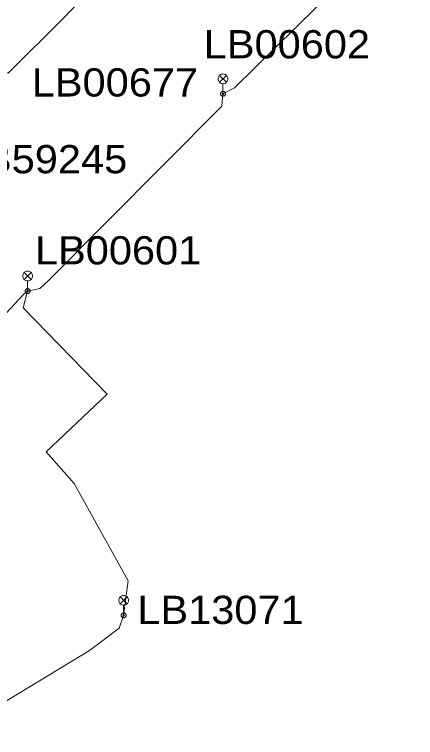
# Model space of a CAD drawing. Extents: x -688049 to -687261, y -973611 to -973038.
# Drawn here: x -687482 to -687451.2, y -973581.7 to -973526.2 of the extents above; entities that cross this region are included whole.
import ezdxf

# ---------------------------------------------------------------- set-up
doc = ezdxf.new("R2010")
doc.units = 0
doc.header["$LTSCALE"] = 0.87
doc.layers.add('1', color=7, linetype='Continuous', lineweight=13)

msp = doc.modelspace()

# ---------------------------------------------------------------- linework, layer by layer
at = {"layer": '1'}
for p, q in [((-687466.235, -973530.865), (-687465.705, -973531.395)), ((-687466.235, -973531.395), (-687465.705, -973530.865)), ((-687465.97, -973532.28), (-687465.97, -973531.505)), ((-687481.225, -973546.005), (-687480.695, -973546.535)), ((-687481.225, -973546.535), (-687480.695, -973546.005)), ((-687480.96, -973547.42), (-687480.96, -973546.645)), ((-687473.855, -973570.905), (-687473.325, -973571.435)), ((-687473.855, -973571.435), (-687473.325, -973570.905)), ((-687473.59, -973572.32), (-687473.59, -973571.545))]:
    msp.add_line(p, q, dxfattribs=at)
for points in [[(-687435.25, -973501.43), (-687435.25, -973502.448), (-687465.092, -973531.834), (-687465.97, -973532.28)], [(-687467.405, -973515.295), (-687467.405, -973515.662), (-687469.111, -973517.285), (-687472.35, -973520.366), (-687478.189, -973526.459), (-687482.459, -973530.691), (-687482.98, -973530.38)], [(-687465.97, -973532.28), (-687466.06, -973533.224), (-687479.338, -973546.595), (-687480.025, -973547.226), (-687480.96, -973547.42)], [(-687480.925, -973547.385), (-687481.31, -973547.725), (-687485.252, -973551.938), (-687492.408, -973546.007), (-687496.766, -973542.227), (-687502.006, -973537.076), (-687502.131, -973537.055)], [(-687473.59, -973572.32), (-687473.238, -973569.66), (-687477.386, -973562.205), (-687479.537, -973559.755), (-687474.856, -973555.338), (-687481.296, -973548.72), (-687480.96, -973547.42)], [(-687488.25, -973581.7), (-687487.316, -973581.393), (-687486.449, -973581.213), (-687476.202, -973575.029), (-687473.932, -973573.292), (-687473.59, -973572.32)]]:
    msp.add_lwpolyline(points, dxfattribs=at)
for points in [[(-687465.595, -973531.13), (-687465.601, -973531.065), (-687465.618, -973531.002), (-687465.645, -973530.942), (-687465.683, -973530.889), (-687465.729, -973530.843), (-687465.782, -973530.805), (-687465.842, -973530.778), (-687465.905, -973530.761), (-687465.97, -973530.755), (-687466.035, -973530.761), (-687466.098, -973530.778), (-687466.158, -973530.805), (-687466.211, -973530.843), (-687466.257, -973530.889), (-687466.295, -973530.942), (-687466.322, -973531.002), (-687466.339, -973531.065), (-687466.345, -973531.13), (-687466.339, -973531.195), (-687466.322, -973531.258), (-687466.295, -973531.318), (-687466.257, -973531.371), (-687466.211, -973531.417), (-687466.158, -973531.455), (-687466.098, -973531.482), (-687466.035, -973531.499), (-687465.97, -973531.505), (-687465.905, -973531.499), (-687465.842, -973531.482), (-687465.782, -973531.455), (-687465.729, -973531.417), (-687465.683, -973531.371), (-687465.645, -973531.318), (-687465.618, -973531.258), (-687465.601, -973531.195)], [(-687465.78, -973532.28), (-687465.783, -973532.247), (-687465.791, -973532.215), (-687465.805, -973532.185), (-687465.824, -973532.158), (-687465.848, -973532.134), (-687465.875, -973532.115), (-687465.905, -973532.101), (-687465.937, -973532.093), (-687465.97, -973532.09), (-687466.003, -973532.093), (-687466.035, -973532.101), (-687466.065, -973532.115), (-687466.092, -973532.134), (-687466.116, -973532.158), (-687466.135, -973532.185), (-687466.149, -973532.215), (-687466.157, -973532.247), (-687466.16, -973532.28), (-687466.157, -973532.313), (-687466.149, -973532.345), (-687466.135, -973532.375), (-687466.116, -973532.402), (-687466.092, -973532.426), (-687466.065, -973532.445), (-687466.035, -973532.459), (-687466.003, -973532.467), (-687465.97, -973532.47), (-687465.937, -973532.467), (-687465.905, -973532.459), (-687465.875, -973532.445), (-687465.848, -973532.426), (-687465.824, -973532.402), (-687465.805, -973532.375), (-687465.791, -973532.345), (-687465.783, -973532.313)], [(-687465.92, -973532.28), (-687465.921, -973532.271), (-687465.923, -973532.263), (-687465.927, -973532.255), (-687465.932, -973532.248), (-687465.938, -973532.242), (-687465.945, -973532.237), (-687465.953, -973532.233), (-687465.961, -973532.231), (-687465.97, -973532.23), (-687465.979, -973532.231), (-687465.987, -973532.233), (-687465.995, -973532.237), (-687466.002, -973532.242), (-687466.008, -973532.248), (-687466.013, -973532.255), (-687466.017, -973532.263), (-687466.019, -973532.271), (-687466.02, -973532.28), (-687466.019, -973532.289), (-687466.017, -973532.297), (-687466.013, -973532.305), (-687466.008, -973532.312), (-687466.002, -973532.318), (-687465.995, -973532.323), (-687465.987, -973532.327), (-687465.979, -973532.329), (-687465.97, -973532.33), (-687465.961, -973532.329), (-687465.953, -973532.327), (-687465.945, -973532.323), (-687465.938, -973532.318), (-687465.932, -973532.312), (-687465.927, -973532.305), (-687465.923, -973532.297), (-687465.921, -973532.289)], [(-687480.585, -973546.27), (-687480.591, -973546.205), (-687480.608, -973546.142), (-687480.635, -973546.082), (-687480.673, -973546.029), (-687480.719, -973545.983), (-687480.772, -973545.945), (-687480.832, -973545.918), (-687480.895, -973545.901), (-687480.96, -973545.895), (-687481.025, -973545.901), (-687481.088, -973545.918), (-687481.148, -973545.945), (-687481.201, -973545.983), (-687481.247, -973546.029), (-687481.285, -973546.082), (-687481.312, -973546.142), (-687481.329, -973546.205), (-687481.335, -973546.27), (-687481.329, -973546.335), (-687481.312, -973546.398), (-687481.285, -973546.458), (-687481.247, -973546.511), (-687481.201, -973546.557), (-687481.148, -973546.595), (-687481.088, -973546.622), (-687481.025, -973546.639), (-687480.96, -973546.645), (-687480.895, -973546.639), (-687480.832, -973546.622), (-687480.772, -973546.595), (-687480.719, -973546.557), (-687480.673, -973546.511), (-687480.635, -973546.458), (-687480.608, -973546.398), (-687480.591, -973546.335)], [(-687480.77, -973547.42), (-687480.773, -973547.387), (-687480.781, -973547.355), (-687480.795, -973547.325), (-687480.814, -973547.298), (-687480.838, -973547.274), (-687480.865, -973547.255), (-687480.895, -973547.241), (-687480.927, -973547.233), (-687480.96, -973547.23), (-687480.993, -973547.233), (-687481.025, -973547.241), (-687481.055, -973547.255), (-687481.082, -973547.274), (-687481.106, -973547.298), (-687481.125, -973547.325), (-687481.139, -973547.355), (-687481.147, -973547.387), (-687481.15, -973547.42), (-687481.147, -973547.453), (-687481.139, -973547.485), (-687481.125, -973547.515), (-687481.106, -973547.542), (-687481.082, -973547.566), (-687481.055, -973547.585), (-687481.025, -973547.599), (-687480.993, -973547.607), (-687480.96, -973547.61), (-687480.927, -973547.607), (-687480.895, -973547.599), (-687480.865, -973547.585), (-687480.838, -973547.566), (-687480.814, -973547.542), (-687480.795, -973547.515), (-687480.781, -973547.485), (-687480.773, -973547.453)], [(-687480.91, -973547.42), (-687480.911, -973547.411), (-687480.913, -973547.403), (-687480.917, -973547.395), (-687480.922, -973547.388), (-687480.928, -973547.382), (-687480.935, -973547.377), (-687480.943, -973547.373), (-687480.951, -973547.371), (-687480.96, -973547.37), (-687480.969, -973547.371), (-687480.977, -973547.373), (-687480.985, -973547.377), (-687480.992, -973547.382), (-687480.998, -973547.388), (-687481.003, -973547.395), (-687481.007, -973547.403), (-687481.009, -973547.411), (-687481.01, -973547.42), (-687481.009, -973547.429), (-687481.007, -973547.437), (-687481.003, -973547.445), (-687480.998, -973547.452), (-687480.992, -973547.458), (-687480.985, -973547.463), (-687480.977, -973547.467), (-687480.969, -973547.469), (-687480.96, -973547.47), (-687480.951, -973547.469), (-687480.943, -973547.467), (-687480.935, -973547.463), (-687480.928, -973547.458), (-687480.922, -973547.452), (-687480.917, -973547.445), (-687480.913, -973547.437), (-687480.911, -973547.429)], [(-687473.215, -973571.17), (-687473.221, -973571.105), (-687473.238, -973571.042), (-687473.265, -973570.982), (-687473.303, -973570.929), (-687473.349, -973570.883), (-687473.402, -973570.845), (-687473.462, -973570.818), (-687473.525, -973570.801), (-687473.59, -973570.795), (-687473.655, -973570.801), (-687473.718, -973570.818), (-687473.778, -973570.845), (-687473.831, -973570.883), (-687473.877, -973570.929), (-687473.915, -973570.982), (-687473.942, -973571.042), (-687473.959, -973571.105), (-687473.965, -973571.17), (-687473.959, -973571.235), (-687473.942, -973571.298), (-687473.915, -973571.357), (-687473.877, -973571.411), (-687473.831, -973571.457), (-687473.778, -973571.495), (-687473.718, -973571.522), (-687473.655, -973571.539), (-687473.59, -973571.545), (-687473.525, -973571.539), (-687473.462, -973571.522), (-687473.402, -973571.495), (-687473.349, -973571.457), (-687473.303, -973571.411), (-687473.265, -973571.357), (-687473.238, -973571.298), (-687473.221, -973571.235)], [(-687473.4, -973572.32), (-687473.403, -973572.287), (-687473.411, -973572.255), (-687473.425, -973572.225), (-687473.444, -973572.198), (-687473.468, -973572.174), (-687473.495, -973572.155), (-687473.525, -973572.141), (-687473.557, -973572.133), (-687473.59, -973572.13), (-687473.623, -973572.133), (-687473.655, -973572.141), (-687473.685, -973572.155), (-687473.712, -973572.174), (-687473.736, -973572.198), (-687473.755, -973572.225), (-687473.769, -973572.255), (-687473.777, -973572.287), (-687473.78, -973572.32), (-687473.777, -973572.353), (-687473.769, -973572.385), (-687473.755, -973572.415), (-687473.736, -973572.442), (-687473.712, -973572.466), (-687473.685, -973572.485), (-687473.655, -973572.499), (-687473.623, -973572.507), (-687473.59, -973572.51), (-687473.557, -973572.507), (-687473.525, -973572.499), (-687473.495, -973572.485), (-687473.468, -973572.466), (-687473.444, -973572.442), (-687473.425, -973572.415), (-687473.411, -973572.385), (-687473.403, -973572.353)], [(-687473.54, -973572.32), (-687473.541, -973572.311), (-687473.543, -973572.303), (-687473.547, -973572.295), (-687473.552, -973572.288), (-687473.558, -973572.282), (-687473.565, -973572.277), (-687473.573, -973572.273), (-687473.581, -973572.271), (-687473.59, -973572.27), (-687473.599, -973572.271), (-687473.607, -973572.273), (-687473.615, -973572.277), (-687473.622, -973572.282), (-687473.628, -973572.288), (-687473.633, -973572.295), (-687473.637, -973572.303), (-687473.639, -973572.311), (-687473.64, -973572.32), (-687473.639, -973572.329), (-687473.637, -973572.337), (-687473.633, -973572.345), (-687473.628, -973572.352), (-687473.622, -973572.358), (-687473.615, -973572.363), (-687473.607, -973572.367), (-687473.599, -973572.369), (-687473.59, -973572.37), (-687473.581, -973572.369), (-687473.573, -973572.367), (-687473.565, -973572.363), (-687473.558, -973572.358), (-687473.552, -973572.352), (-687473.547, -973572.345), (-687473.543, -973572.337), (-687473.541, -973572.329)]]:
    msp.add_lwpolyline(points, close=True, dxfattribs=at)

# ---------------------------------------------------------------- texts
at = {"layer": '1', "width": 1.1}
for s, height, p in [('LB00602', 2.167, (-687467.441, -973529.56)), ('LB00677', 2.167, (-687480.641, -973532.489)), ('LB59245', 2.168, (-687486.084, -973538.381)), ('LB00601', 2.167, (-687480.397, -973545.38)), ('LB13071', 2.167, (-687472.538, -973572.982))]:
    msp.add_text(s, height=height, dxfattribs=at).set_placement(p)

doc.saveas('drawing.dxf')
